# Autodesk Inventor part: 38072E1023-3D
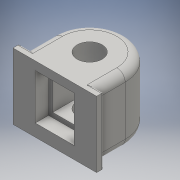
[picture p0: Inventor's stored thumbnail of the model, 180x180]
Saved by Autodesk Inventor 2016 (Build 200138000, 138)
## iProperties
Created: 2018-07
Part Number: 38072E1023-3D
Material: 일반
Document SubType Name: Modeling
Designer: 201-13
Density: 1 g/cm^3
Appearance: 기본값
Author: 201-13
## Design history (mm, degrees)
sketch "스케치1"
  geometry: L1 (51, 50)-(51, 10); L2 (51, 0)-(-51, 0); L3 (-51, 50)-(-51, 10); L4 (-60, 0)-(60, 0); L5 (60, 0)-(60, 10); L6 (-60, 10)-(-60, 0); L7 (60, 10)-(51, 10); L8 (-51, 10)-(-60, 10); C1 r 18 at (0, 50); A1 r 51 centre (0, 50) between (51, 50) and (-51, 50); 1 further point
  constraints: 16 end point, 3 parallel, 2 centre point, 2 perpendicular, 2 point on circle, 2 tangent, 2 vertical, 1 coincident, 1 horizontal
  dimensions: "d0" = 102 diameter of A1; "d2" = 36 diameter of C1; "d4" = 50 distance from line of L2 A1.centre; "d5" = 10 distance of L6.start L4.start; "d6" = 60 distance from line of point (0, 0) L6; "d7" = 60 distance from line of L5 point (0, 0)
extrude "돌출1" new body sketch "스케치1" distance "d8" = 95; taper "d9" = 0 deg
fillet "모깎기1" dims "d10" = 12
sketch "스케치2"
  geometry: L1 (38, 76.613)-(82, 76.613); L2 (82, 76.613)-(82, 24.46); L3 (82, 24.46)-(38, 24.46); L4 (38, 24.46)-(38, 76.613); L5 (0, 0)-(0, 95) reference; 1 further point
  constraints: 8 end point, 2 parallel, 1 horizontal, 1 perpendicular
  dimensions: "d11" = 44 distance of L1.start L1.end; "d12" = 38 distance between parallel lines of L5 L4
extrude "돌출2" cut sketch "스케치2" distance "d13" = 50; taper "d14" = 0 deg
fillet "모깎기2" dims "d15" = 3
sketch "스케치3"
  geometry: L1 (111, 83)-(9, 83) reference; L2 (32, 17.711)-(88, 17.711); L3 (88, 17.711)-(88, 83); L4 (88, 83)-(32, 83); L5 (32, 83)-(32, 17.711); L6 (0, 0)-(0, 95) reference; 1 further point
  constraints: 8 end point, 2 parallel, 1 horizontal, 1 perpendicular, 1 point on line
  dimensions: "d16" = 56 distance of L2.start L2.end; "d17" = 32 distance between parallel lines of L6 L5
extrude "돌출3" cut sketch "스케치3" distance "d18" = 19; taper "d19" = 0 deg
node "솔리드1"
